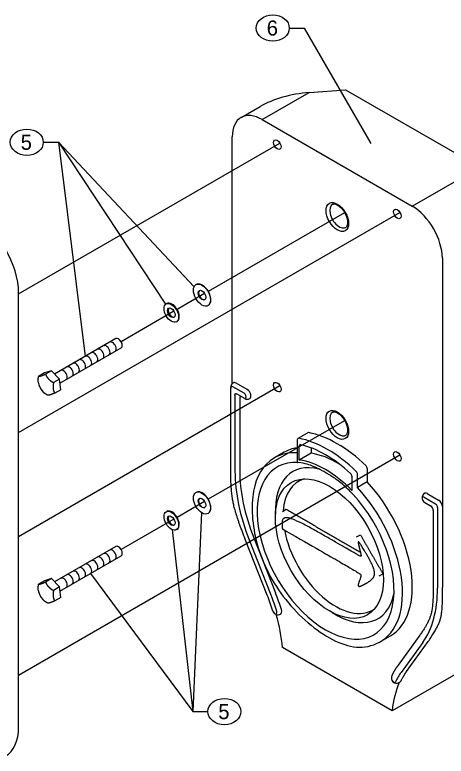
# Model space of a CAD drawing. Extents: x 99862 to 103151, y 100000 to 105076.
# Drawn here: x 101353 to 101811, y 100419 to 101205 of the extents above; entities that cross this region are included whole.
import ezdxf

# ---------------------------------------------------------------- set-up
doc = ezdxf.new("R2010")
doc.units = 0
for name, color, linetype in [('Level 15', 7, 'Continuous'), ('Level 16', 7, 'Continuous'), ('Level 20', 7, 'Continuous'), ('Level 33', 7, 'Continuous'), ('Level 34', 7, 'Continuous'), ('Level 35', 7, 'Continuous'), ('Level 36', 7, 'Continuous'), ('Level 38', 7, 'Continuous'), ('Level 41', 7, 'Continuous')]:
    doc.layers.add(name, color=color, linetype=linetype)

msp = doc.modelspace()

# ---------------------------------------------------------------- linework, layer by layer
at = {"layer": 'Level 15'}
for p, q in [((101644.5, 101191.1), (101660.5, 101191.1)), ((101731.18, 101068.68), (101660.5, 101191.1)), ((101383.7, 101069.95), (101399.7, 101069.95)), ((101399.7, 101069.95), (101428.18, 100842.92)), ((101399.7, 101069.95), (101543.52, 100916.8)), ((101399.7, 101069.95), (101513.38, 100898.17)), ((101551.47, 100677.16), (101542.21, 100466.16)), ((101520.46, 100659.18), (101542.21, 100466.16)), ((101433.81, 100612.72), (101542.21, 100466.16)), ((101542.21, 100466.16), (101558.21, 100466.16))]:
    msp.add_line(p, q, dxfattribs=at)
at = {"layer": 'Level 16'}
for p, q in [((101357.47, 100909.08), (101634.56, 101069.05)), ((101357.47, 100762.11), (101761.84, 100995.57)), ((101703.1, 100995.15), (101558.64, 100911.75)), ((101554.73, 100909.49), (101525.53, 100892.63)), ((101522.2, 100890.71), (101466.3, 100858.43)), ((101357.47, 100651.88), (101634.56, 100811.86)), ((101703.1, 100774.7), (101558.64, 100691.29)), ((101357.47, 100504.91), (101761.84, 100738.37)), ((101554.73, 100689.04), (101525.53, 100672.18)), ((101522.2, 100670.26), (101466.3, 100637.98))]:
    msp.add_line(p, q, dxfattribs=at)
at = {"layer": 'Level 20'}
for centre in [(101627, 101191.1), (101366.2, 101069.95), (101575.71, 100466.16)]:
    msp.add_ellipse(centre, major_axis=(-17.5, 0), ratio=0.8, dxfattribs=at)
at = {"layer": 'Level 33'}
for p, q in [((101615.83, 101093.94), (101665.66, 101122.71)), ((101665.66, 101122.71), (101703.98, 101125.72)), ((101703.98, 101125.72), (101829.98, 101052.98)), ((101593.33, 101096.17), (101613.55, 101107.84)), ((101615.83, 101093.94), (101774.93, 101002.09)), ((101584.01, 100813.92), (101584.01, 101075.57)), ((101774.93, 101002.09), (101824.75, 101030.85)), ((101704.4, 100979.67), (101704.4, 100979.67)), ((101806.75, 100946.97), (101806.75, 100683.64)), ((101582.37, 100724.22), (101582.37, 100809.94)), ((101596.62, 100803.7), (101584.69, 100810.59)), ((101599.92, 100807.65), (101587.99, 100814.54)), ((101586.9, 100801.64), (101586.9, 100721.04)), ((101596.62, 100798.59), (101589.12, 100802.92)), ((101591.97, 100798.46), (101591.97, 100721.93)), ((101664.15, 100761.95), (101654.31, 100756.28)), ((101652.86, 100753.41), (101652.86, 100730.87)), ((101704.4, 100759.21), (101704.4, 100759.21)), ((101655.13, 100732.94), (101655.13, 100747.85)), ((101667.54, 100745.88), (101667.54, 100740.11)), ((101639.13, 100741.28), (101628.74, 100735.28)), ((101667.54, 100740.11), (101655.13, 100732.94)), ((101727.2, 100723.92), (101727.2, 100709.67)), ((101710.82, 100715.7), (101710.82, 100700.79)), ((101716.81, 100703.66), (101716.79, 100717.91)), ((101727.2, 100709.67), (101716.81, 100703.66)), ((101790.84, 100697.42), (101802.78, 100690.53)), ((101787.54, 100693.48), (101799.47, 100686.59)), ((101788.03, 100687.95), (101794.34, 100684.31)), ((101801.69, 100682.75), (101801.69, 100597.03)), ((101806.75, 100683.64), (101806.75, 100597.92)), ((101797.15, 100679.44), (101797.15, 100600.22)), ((101606.87, 100650.32), (101629.82, 100592.13)), ((101621.19, 100589.66), (101598.23, 100647.85)), ((101602.04, 100648.25), (101625, 100590.06)), ((101741.24, 100540.42), (101751.63, 100546.42)), ((101782.77, 100547.09), (101759.81, 100515.41)), ((101768.92, 100508.81), (101791.88, 100540.49)), ((101753.56, 100466.99), (101637.21, 100534.17)), ((101785.93, 100539.48), (101762.97, 100507.81)), ((101825.15, 100508.33), (101753.56, 100466.99))]:
    msp.add_line(p, q, dxfattribs=at)
for centre, start, end in [((101587.99, 100809.94), 120, 135.03838), ((101587.99, 100809.94), 135.05052, 180), ((101599.92, 100803.05), 240, 300), ((101790.84, 100692.83), 120, 240), ((101791.53, 100679.44), 360, 60), ((101632.48, 100574.53), 197.2909, 251.93927), ((101632.48, 100574.53), 251.93932, 300), ((101758.28, 100501.9), 154.08148, 299.62181), ((101758.28, 100501.9), 299.62181, 328.21805)]:
    msp.add_arc(centre, 5.63, start, end, dxfattribs=at)
for centre, major_axis, ratio, start_param, end_param in [((101665.66, 101085.96), (73.59, 7.69), 0.494566, 1.519169, 2.304567), ((101615.83, 101057.2), (-22.5, 38.97), 0.57735, 5.497787, 6.283185), ((101615.83, 101057.2), (-22.5, 38.97), 0.57735, 6.283185, 7.068583), ((101697.37, 100991.84), (-7.03, 12.18), 0.57735, 6.244605, 9.508637), ((101774.93, 100965.34), (22.5, -38.97), 0.57735, 0.785398, 2.356194), ((101587.99, 100809.94), (-2.81, 4.87), 0.57735, 5.497787, 6.283185), ((101584.69, 100808.03), (1.57, -2.71), 0.57735, 2.356194, 3.926991), ((101599.92, 100803.05), (-2.81, 4.87), 0.57735, 3.141593, 5.497787), ((101595.95, 100796.16), (-2.81, 4.87), 0.57735, 0.159548, 0.785398), ((101596.62, 100801.15), (1.57, -2.71), 0.57735, 5.497787, 8.63938), ((101697.37, 100771.39), (-7.03, 12.18), 0.57735, 6.244605, 9.508637), ((101665.55, 100759.52), (-1.41, 2.44), 0.57735, 5.822618, 6.283185), ((101695.38, 100640.01), (-67.5, 116.91), 0.57735, 5.172956, 5.822618), ((101654.95, 100753.73), (0.52, 2.76), 0.731418, 0.561152, 1.823018), ((101684.97, 100633.99), (67.5, -116.91), 0.57735, 2.031363, 2.681026), ((101695.38, 100643.85), (-56.25, 97.43), 0.57735, 6.069803, 6.28319), ((101657.12, 100746.7), (1.41, -2.44), 0.57735, 2.649261, 3.926991), ((101682.98, 100632.85), (64.69, -112.04), 0.57735, 2.063128, 2.649261), ((101684.99, 100637.85), (56.25, -97.43), 0.57735, 2.771884, 3.141593), ((101695.38, 100640.01), (-55.09, 95.42), 0.57735, 5.467511, 5.86323), ((101683, 100636.7), (51.31, -88.87), 0.57735, 2.770312, 8.225262), ((101653.17, 100730.7), (0.215, -0.372), 0.57735, 3.926991, 5.90159), ((101682.98, 100632.85), (55.09, -95.42), 0.57735, 1.990752, 2.721637), ((101696.06, 100658.02), (-77.18, 133.69), 0.57735, 0.785398, 1.318407), ((101699.36, 100659.92), (75.94, -131.53), 0.57735, 3.926991, 4.46), ((101714.8, 100719.06), (-1.41, 2.44), 0.57735, 3.926991, 5.172956), ((101725.22, 100725.07), (-1.41, 2.44), 0.57735, 3.926991, 5.172956), ((101708.83, 100716.85), (1.41, -2.44), 0.57735, 0.785398, 2.063128), ((101695.38, 100643.85), (-56.25, 97.43), 0.57735, 3.141593, 5.08627), ((101684.99, 100637.85), (56.25, -97.43), 0.57735, 6.254516, 8.227863), ((101790.84, 100692.83), (-2.81, 4.87), 0.57735, 5.497787, 6.283185), ((101787.54, 100690.92), (1.57, -2.71), 0.57735, 2.356194, 4.712389), ((101802.78, 100685.94), (-2.81, 4.87), 0.57735, 3.926991, 5.497787), ((101799.47, 100684.03), (1.57, -2.71), 0.57735, 0.785398, 2.356194), ((101688.1, 100662.61), (80.32, -139.11), 0.57735, 0.252389, 0.785398), ((101527.17, 100579.9), (-77.18, 133.69), 0.57735, 4.339992, 4.46), ((101527.17, 100579.9), (80.32, -139.11), 0.57735, 1.198399, 1.318408), ((101530.48, 100581.81), (-81.56, 141.27), 0.57735, 4.339992, 4.46), ((101629.18, 100572.62), (1.57, -2.71), 0.57735, 4.339992, 7.481585), ((101632.48, 100574.53), (-2.81, 4.87), 0.57735, 3.141594, 4.339992), ((101526.5, 100584.1), (-78.75, 136.4), 0.57735, 4.035936, 4.286649), ((101856.99, 100389.48), (-77.18, 133.69), 0.57735, 0.252389, 0.372397), ((101754.98, 100499.99), (1.57, -2.71), 0.57735, 4.712389, 6.655582), ((101864.27, 100389.09), (-78.75, 136.4), 0.57735, 0.400156, 0.676453)]:
    msp.add_ellipse(centre, major_axis=major_axis, ratio=ratio, start_param=start_param, end_param=end_param, dxfattribs=at)
for centre, major_axis in [((101631.74, 101067.43), (-2.81, 4.87)), ((101695.38, 100990.7), (-8.44, 14.61)), ((101759.02, 100993.95), (-2.81, 4.87)), ((101631.74, 100810.23), (-2.81, 4.87)), ((101695.38, 100770.24), (-8.44, 14.61)), ((101759.02, 100736.75), (-2.81, 4.87))]:
    msp.add_ellipse(centre, major_axis=major_axis, ratio=0.57735, dxfattribs=at)
for points, degree in [([(101690.62, 101004.17), (101691.69, 101004.65), (101693.59, 101004.56), (101695.97, 101003.19)], 2), ([(101695.97, 101003.19), (101701.09, 101000.31), (101708.17, 100987.26), (101705.87, 100980.91), (101704.97, 100980.05)], 3), ([(101586.9, 100801.64), (101586.9, 100801.92), (101586.92, 100802.2), (101586.96, 100802.45), (101587.01, 100802.7), (101587.09, 100802.93), (101587.21, 100803.1), (101587.3, 100803.21), (101587.41, 100803.3), (101587.53, 100803.34), (101587.66, 100803.39), (101587.8, 100803.4), (101587.95, 100803.38), (101588.2, 100803.35), (101588.48, 100803.25), (101588.75, 100803.12), (101588.87, 100803.06), (101588.99, 100802.99), (101589.12, 100802.92)], 3), ([(101690.62, 100783.72), (101691.69, 100784.2), (101693.59, 100784.11), (101695.97, 100782.73)], 2), ([(101695.97, 100782.73), (101701.09, 100779.86), (101708.17, 100766.8), (101705.87, 100760.45), (101704.97, 100759.6)], 3), ([(101628.74, 100735.28), (101615.76, 100727.2), (101602.9, 100704.22), (101605.73, 100643.79), (101636.91, 100582.48), (101691.17, 100536), (101724.2, 100531.34), (101739.98, 100539.72)], 3), ([(101712.2, 100696.55), (101707.59, 100701.43), (101702.79, 100705.86), (101695.48, 100711.59), (101693.03, 100713.32), (101688.18, 100716.52), (101685.78, 100717.99), (101680.79, 100720.88), (101678.19, 100722.28), (101673.1, 100724.83), (101670.61, 100725.94), (101663.25, 100728.71), (101658.44, 100729.82), (101653.8, 100730.26)], 3), ([(101598.21, 100647.89), (101587.89, 100673.99), (101582.34, 100700.58), (101582.37, 100724.22)], 2), ([(101797.15, 100600.22), (101797.18, 100578.28), (101791.99, 100559.72), (101782.77, 100547.09)], 2), ([(101791.88, 100540.49), (101802.76, 100556.19), (101807.45, 100575.45), (101806.75, 100597.92)], 2), ([(101759.81, 100515.41), (101757.35, 100512.01), (101755.15, 100508.32), (101753.22, 100504.36)], 2), ([(101763.07, 100498.93), (101766.07, 100504.59), (101767.45, 100506.78), (101768.92, 100508.81)], 2)]:
    msp.add_open_spline(points, degree=degree, dxfattribs=at)
at = {"layer": 'Level 34'}
for start_param, end_param in [(2.632698, 3.978331), (5.446447, 6.851151)]:
    msp.add_ellipse((101693.34, 100642.67), major_axis=(45, -77.94), ratio=0.57735, start_param=start_param, end_param=end_param, dxfattribs=at)
msp.add_ellipse((101686.98, 100639), major_axis=(40.5, -70.15), ratio=0.57735, dxfattribs=at)
at = {"layer": 'Level 35'}
for p, q in [((101637.21, 100678.44), (101641.19, 100680.74)), ((101715.86, 100651.4), (101719.84, 100653.7)), ((101739.73, 100610.07), (101743.7, 100612.37))]:
    msp.add_line(p, q, dxfattribs=at)
for points, degree in [([(101641.19, 100680.74), (101680.51, 100658.03), (101719.84, 100635.33)], 2), ([(101637.21, 100660.07), (101635.97, 100669.97), (101637.21, 100678.44), (101677.81, 100655), (101718.4, 100631.56), (101721.16, 100629.97), (101720.29, 100633.5), (101718.08, 100642.45), (101715.86, 100651.4), (101727.79, 100630.74), (101739.73, 100610.07), (101727.79, 100603.18), (101715.86, 100596.29), (101718.08, 100602.69), (101720.29, 100609.08), (101721.16, 100611.6), (101718.4, 100613.19), (101677.81, 100636.63), (101637.21, 100660.07)], 4), ([(101719.84, 100653.7), (101731.77, 100633.03), (101743.7, 100612.37)], 2)]:
    msp.add_open_spline(points, degree=degree, dxfattribs=at)
at = {"layer": 'Level 36'}
msp.add_line((101743.6, 100612.31), (101743.63, 100612.32), dxfattribs=at)
for start_param, end_param in [(2.991971, 3.85234), (4.156158, 6.332503)]:
    msp.add_ellipse((101693.63, 100642.1), major_axis=(39.38, -68.2), ratio=0.57735, start_param=start_param, end_param=end_param, dxfattribs=at)
at = {"layer": 'Level 38'}
for p, q in [((101514.6, 100898.94), (101513.93, 100898.55)), ((101524.86, 100879.62), (101525.53, 100880.01)), ((101460.67, 100861.68), (101395.68, 100824.16)), ((101401.31, 100814.42), (101466.3, 100851.94)), ((101385.06, 100825.34), (101378.76, 100821.7)), ((101392.3, 100827.69), (101385.06, 100825.34)), ((101392.3, 100827.69), (101386, 100824.05)), ((101400.82, 100818.8), (101392.3, 100827.69)), ((101400.82, 100818.8), (101394.51, 100815.16)), ((101402.09, 100807.56), (101400.82, 100818.8)), ((101402.09, 100807.56), (101395.79, 100803.92)), ((101460.67, 100641.23), (101395.68, 100603.7)), ((101401.31, 100593.97), (101466.3, 100631.48)), ((101385.06, 100604.89), (101378.76, 100601.25)), ((101392.3, 100607.24), (101385.06, 100604.89)), ((101392.3, 100607.24), (101386, 100603.6)), ((101400.82, 100598.35), (101392.3, 100607.24)), ((101400.82, 100598.35), (101394.51, 100594.71)), ((101402.09, 100587.1), (101400.82, 100598.35)), ((101402.09, 100587.1), (101395.79, 100583.46))]:
    msp.add_line(p, q, dxfattribs=at)
for centre, major_axis in [((101551.92, 100907.87), (-6.44, 11.16)), ((101551.92, 100907.87), (2.81, -4.87)), ((101519.39, 100889.09), (-5.46, 9.46)), ((101519.39, 100889.09), (2.81, -4.87)), ((101551.92, 100687.41), (-6.44, 11.16)), ((101551.92, 100687.41), (2.81, -4.87)), ((101519.39, 100668.63), (-5.46, 9.46)), ((101519.39, 100668.63), (2.81, -4.87))]:
    msp.add_ellipse(centre, major_axis=major_axis, ratio=0.57735, dxfattribs=at)
for centre, major_axis, start_param, end_param in [((101552.2, 100908.03), (-6.44, 11.16), 3.119941, 6.283185), ((101552.2, 100908.03), (2.81, -4.87), 3.19121, 6.233568), ((101520.07, 100889.48), (-5.46, 9.46), 3.141593, 6.28318), ((101520.07, 100889.48), (2.81, -4.87), 3.26164, 6.163138), ((101463.48, 100856.81), (-2.81, 4.87), 3.141591, 6.283173), ((101450.5, 100849.31), (2.81, -4.87), 6.28318, 9.424778), ((101450.5, 100849.31), (2.81, -4.87), 3.141593, 3.141605), ((101453.74, 100851.19), (2.81, -4.87), 3.141593, 3.141605), ((101456.99, 100853.06), (2.81, -4.87), 6.28318, 9.424778), ((101456.99, 100853.06), (2.81, -4.87), 3.141593, 3.141605), ((101460.24, 100854.93), (2.81, -4.87), 3.141593, 3.141605), ((101463.48, 100856.81), (-2.81, 4.87), 6.283173, 6.283185), ((101437.51, 100841.81), (2.81, -4.87), 6.28318, 9.424778), ((101437.51, 100841.81), (2.81, -4.87), 3.141593, 3.141605), ((101440.76, 100843.69), (2.81, -4.87), 3.141593, 3.141605), ((101444, 100845.56), (2.81, -4.87), 6.28318, 9.424778), ((101444, 100845.56), (2.81, -4.87), 3.141593, 3.141605), ((101447.25, 100847.44), (2.81, -4.87), 3.141593, 3.141605), ((101424.52, 100834.31), (2.81, -4.87), 6.28318, 9.424778), ((101424.52, 100834.31), (2.81, -4.87), 3.141593, 3.141605), ((101427.77, 100836.19), (2.81, -4.87), 3.141593, 3.141605), ((101431.02, 100838.06), (2.81, -4.87), 6.28318, 9.424778), ((101431.02, 100838.06), (2.81, -4.87), 3.141593, 3.141605), ((101434.26, 100839.94), (2.81, -4.87), 3.141593, 3.141605), ((101411.53, 100826.82), (2.81, -4.87), 6.28318, 9.424778), ((101411.53, 100826.82), (2.81, -4.87), 3.141593, 3.141605), ((101414.78, 100828.69), (2.81, -4.87), 3.141593, 3.141605), ((101418.03, 100830.56), (2.81, -4.87), 6.28318, 9.424778), ((101418.03, 100830.56), (2.81, -4.87), 3.141593, 3.141605), ((101421.27, 100832.44), (2.81, -4.87), 3.141593, 3.141605), ((101405.04, 100823.07), (2.81, -4.87), 6.28318, 9.424778), ((101405.04, 100823.07), (2.81, -4.87), 3.141593, 3.141605), ((101408.29, 100824.94), (2.81, -4.87), 3.141593, 3.141605), ((101386.25, 100812.22), (5.63, -9.74), 4.066603, 5.113801), ((101552.2, 100687.57), (-6.44, 11.16), 4.16506, 6.304836), ((101552.2, 100687.57), (2.81, -4.87), 3.19121, 6.233568), ((101552.2, 100687.57), (-6.44, 11.16), 3.119941, 4.16506), ((101520.07, 100669.02), (-5.46, 9.46), 3.079907, 6.344871), ((101520.07, 100669.02), (2.81, -4.87), 3.26164, 6.163138), ((101463.48, 100636.36), (-2.81, 4.87), 3.141591, 6.283173), ((101450.5, 100628.86), (2.81, -4.87), 6.28318, 9.424778), ((101453.74, 100630.73), (2.81, -4.87), 3.141593, 3.141605), ((101456.99, 100632.61), (2.81, -4.87), 6.28318, 9.424778), ((101456.99, 100632.61), (2.81, -4.87), 3.141593, 3.141605), ((101460.24, 100634.48), (2.81, -4.87), 3.141593, 3.141605), ((101463.48, 100636.36), (-2.81, 4.87), 6.283173, 6.283185), ((101437.51, 100621.36), (2.81, -4.87), 6.28318, 9.424778), ((101437.51, 100621.36), (2.81, -4.87), 3.141593, 3.141605), ((101440.76, 100623.23), (2.81, -4.87), 3.141593, 3.141605), ((101444, 100625.11), (2.81, -4.87), 6.28318, 9.424778), ((101444, 100625.11), (2.81, -4.87), 3.141593, 3.141605), ((101447.25, 100626.98), (2.81, -4.87), 3.141593, 3.141605), ((101450.5, 100628.86), (2.81, -4.87), 3.141593, 3.141605), ((101424.52, 100613.86), (2.81, -4.87), 6.28318, 9.424778), ((101424.52, 100613.86), (2.81, -4.87), 3.141593, 3.141605), ((101427.77, 100615.73), (2.81, -4.87), 3.141593, 3.141605), ((101431.02, 100617.61), (2.81, -4.87), 6.28318, 9.424778), ((101431.02, 100617.61), (2.81, -4.87), 3.141593, 3.141605), ((101434.26, 100619.48), (2.81, -4.87), 3.141593, 3.141605), ((101411.53, 100606.36), (2.81, -4.87), 6.28318, 9.424778), ((101411.53, 100606.36), (2.81, -4.87), 3.141593, 3.141605), ((101414.78, 100608.24), (2.81, -4.87), 3.141593, 3.141605), ((101418.03, 100610.11), (2.81, -4.87), 6.28318, 9.424778), ((101418.03, 100610.11), (2.81, -4.87), 3.141593, 3.141605), ((101421.27, 100611.99), (2.81, -4.87), 3.141593, 3.141605), ((101405.04, 100602.61), (2.81, -4.87), 6.28318, 9.424778), ((101405.04, 100602.61), (2.81, -4.87), 3.141593, 3.141605), ((101408.29, 100604.49), (2.81, -4.87), 3.141593, 3.141605), ((101386.25, 100591.76), (5.63, -9.74), 4.066603, 5.113801)]:
    msp.add_ellipse(centre, major_axis=major_axis, ratio=0.57735, start_param=start_param, end_param=end_param, dxfattribs=at)
for points in [[(101381.35, 100822.28), (101382.6, 100822.69), (101384.23, 100823.32), (101386, 100824.05)], [(101386, 100824.05), (101386.74, 100822.28), (101387.77, 100820.54), (101389.23, 100819.01)], [(101378.37, 100815.49), (101378.15, 100817.42), (101378.35, 100819.55), (101378.76, 100821.7)], [(101378.76, 100821.7), (101379.3, 100821.72), (101380.11, 100821.88), (101381.35, 100822.28)], [(101389.23, 100819.01), (101390.69, 100817.48), (101392.54, 100816.23), (101394.51, 100815.16)], [(101394.51, 100815.16), (101394.11, 100813.02), (101393.91, 100810.88), (101394.13, 100808.95)], [(101394.13, 100808.95), (101394.35, 100807.01), (101394.97, 100805.36), (101395.79, 100803.92)], [(101388.55, 100801.57), (101386.58, 100802.63), (101384.73, 100803.9), (101383.27, 100805.42)], [(101391.15, 100802.15), (101389.9, 100801.75), (101389.1, 100801.59), (101388.55, 100801.57)], [(101395.79, 100803.92), (101394.03, 100803.19), (101392.39, 100802.55), (101391.15, 100802.15)], [(101381.35, 100601.83), (101382.6, 100602.23), (101384.23, 100602.87), (101386, 100603.6)], [(101386, 100603.6), (101386.74, 100601.83), (101387.77, 100600.08), (101389.23, 100598.56)], [(101378.37, 100595.03), (101378.15, 100596.97), (101378.35, 100599.09), (101378.76, 100601.25)], [(101378.76, 100601.25), (101379.3, 100601.27), (101380.11, 100601.43), (101381.35, 100601.83)], [(101389.23, 100598.56), (101390.69, 100597.03), (101392.54, 100595.78), (101394.51, 100594.71)], [(101394.51, 100594.71), (101394.11, 100592.56), (101393.91, 100590.42), (101394.13, 100588.49)], [(101394.13, 100588.49), (101394.35, 100586.56), (101394.97, 100584.91), (101395.79, 100583.46)], [(101388.55, 100581.11), (101386.58, 100582.18), (101384.73, 100583.44), (101383.27, 100584.97)], [(101391.15, 100581.7), (101389.9, 100581.29), (101389.1, 100581.14), (101388.55, 100581.11)], [(101395.79, 100583.46), (101394.03, 100582.74), (101392.39, 100582.1), (101391.15, 100581.7)]]:
    msp.add_open_spline(points, degree=2, dxfattribs=at)
at = {"layer": 'Level 41'}
msp.add_line((101357.47, 100449.8), (101357.47, 100909.81), dxfattribs=at)
for centre, major_axis, start_param, end_param in [((101309.74, 100937.37), (-33.75, 58.46), 3.926991, 5.497787), ((101309.74, 100477.35), (33.75, -58.46), 0, 0.785398)]:
    msp.add_ellipse(centre, major_axis=major_axis, ratio=0.57735, start_param=start_param, end_param=end_param, dxfattribs=at)

# ---------------------------------------------------------------- texts
at = {"layer": 'Level 20'}
for s, p in [('6', (101620.57, 101183.1)), ('5', (101359.71, 101061.95)), ('5', (101569.22, 100458.16))]:
    msp.add_text(s, height=16, dxfattribs=at).set_placement(p)

doc.saveas('drawing.dxf')
